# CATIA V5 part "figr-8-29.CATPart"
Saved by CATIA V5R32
Part number: Part1
Bounding box of the stored display mesh (mm): x 37.5 to 207.5, y 10 to 85, z 0 to 113
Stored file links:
  D:\PROJECTS\Project 2022\CATIA V5 6R 2022\Resources\Part Files\c08_catia_v5_6r2022_prt\figr-8-29.CATPart
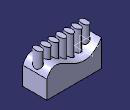
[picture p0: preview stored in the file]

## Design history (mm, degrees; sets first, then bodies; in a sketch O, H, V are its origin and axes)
Set1
  Plane1: type Offset, RefPlane xy-plane, Offset 113
Body1 (main body)
  Sketch1 on xy-plane, origin (0, 0, 0), H (1, 0, 0), V (0, 1, 0)
    line L1 (-37.5, 85) -> (37.5, 85)
    line L2 (37.5, 85) -> (37.5, -85)
    line L3 (37.5, -85) -> (-37.5, -85)
    line L4 (-37.5, -85) -> (-37.5, 85)
    axis line L5 (37.5, -85) -> (-37.5, 85)
    length L3 = 75
    length L2 = 170
    horizontal: L1 H, L3 H
    vertical: L2 V, L4 V
    midpoint: O L5
  Pad1: profile Sketch1, direction (0, 0, 1), length 83
  Sketch2 on face of Pad1, origin (37.5, 0, 0), H (0, 1, 0), V (0, 0, 1)
    spline S1 through (-85, 56.7422) (-58.5369, 80.0687) (-27.7952, 70.201) (85, 83)
    reference projected line E1 (85, 0) -> (85, 83) from edge [face of Pad1 | face of Pad1]
    reference projected line E2 (-85, 0) -> (-85, 83) from edge [face of Pad1 | face of Pad1]
    reference projected line E3 (-85, 83) -> (85, 83) from edge [face of Pad1 | face of Pad1]
    point P1 (85, 83)
    point P3 (-85, 56.7422)
    coincidence: P1 E1, P3 E2, P1 E3
  Pocket1: profile Sketch2, direction (-1, 0, 0), length 83
  Rotate1: Axis edge [face of Pad1 | face of Pad1], ToTransfor Pocket1, Angle 90
  Sketch3 on Plane1, origin (0, 0, 113), H (1, 0, 0), V (0, 1, 0)
    ellipse A1 centre (195.4286, 45.9861) semi-axes 14.9247, 8.8005 rotation 90
  Pad2: profile Sketch3, direction (0, 0, -1), up to face of Pocket1
  RectPattern1: of Pad2, direction 1 instances 7, spacing 24, along edge [face of Pad1 | face of Pad1]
